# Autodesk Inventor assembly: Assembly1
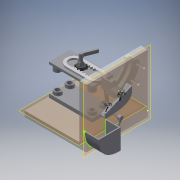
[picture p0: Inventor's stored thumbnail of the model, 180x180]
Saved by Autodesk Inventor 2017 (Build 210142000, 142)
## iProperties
Created: 2017-04
Part Number: Assembly1
Document SubType Name: Assembly
Designer: 1460374
Author: 1460374
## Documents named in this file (18)
- R:\STEM 1st Pd\JacobPatCandy\Assembly1.iam
- R:\STEM 1st Pd\JacobPatCandy\BasePlate.ipt
- R:\STEM 1st Pd\JacobPatCandy\RampV2.ipt
- R:\STEM 1st Pd\JacobPatCandy\RampPlate.ipt
- R:\STEM 1st Pd\JacobPatCandy\platform.ipt
- R:\STEM 1st Pd\JacobPatCandy\guard.ipt
- R:\STEM 1st Pd\JacobPatCandy\Connector.ipt
- R:\STEM 1st Pd\JacobPatCandy\Gearv2.ipt
- R:\STEM 1st Pd\JacobPatCandy\handle.ipt
- R:\STEM 1st Pd\JacobPatCandy\platform2.ipt
- R:\STEM 1st Pd\JacobPatCandy\platform2_2.ipt
- R:\STEM 1st Pd\JacobPatCandy\push.ipt
- R:\STEM 1st Pd\JacobPatCandy\SwirlPiece.ipt
- R:\STEM 1st Pd\JacobPatCandy\SwirlPath.ipt
- R:\STEM 1st Pd\JacobPatCandy\partial_gear.ipt
- R:\STEM 1st Pd\JacobPatCandy\gear handle.ipt
- R:\STEM 1st Pd\JacobPatCandy\SwirlWall.ipt
- R:\STEM 1st Pd\JacobPatCandy\BowlV2.ipt
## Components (17 placed, 17 different names)
1. BasePlate:1 — Mate:8, Mate:9, Mate:10, Mate:11, Mate:12, Mate:23, Mate:28, Mate:31, Mate:32, Mate:35, Flush:5, Mate:47, Mate:50, Flush:19, Flush:20
2. RampV2:1 — Mate:5, Mate:6, Mate:7, Mate:8, Mate:9, Flush:1, Mate:49
3. RampPlate:1 — Mate:5, Mate:6, Mate:7
4. platform:1 — Mate:47, Mate:48, Flush:17, Mate:49
5. guard:1 — Flush:1, Mate:10, Mate:11, Mate:12
6. Connector:1 — Mate:30, Mate:48, Flush:17
7. Gearv2:1 — Mate:23, Mate:25, Mate:26, Mate:28, Mate:30, Mate:32
8. handle:1 — Mate:25, Mate:26, Mate:31
9. platform2:1
10. platform2_2:1 — Mate:44, Mate:45, Mate:46
11. push:1 — Mate:35, Mate:44
12. SwirlPiece:1 — Flush:5
13. SwirlPath:1 — Mate:50, Flush:18
14. partial_gear:1 — Mate:41, Mate:42, Mate:43, Mate:45, Mate:46
15. gear handle:1 — Mate:41, Mate:42, Mate:43
16. SwirlWall:1 — Flush:18
17. BowlV2:1 — Flush:19, Flush:20
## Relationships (32: Mate 26, Flush 6)
- Mate:5: RampV2:1 ↔ RampPlate:1
- Mate:6: RampV2:1 ↔ RampPlate:1
- Mate:7: RampV2:1 ↔ RampPlate:1
- Mate:8: BasePlate:1 ↔ RampV2:1
- Mate:9: BasePlate:1 ↔ RampV2:1
- Flush:1: RampV2:1 ↔ guard:1
- Mate:10: BasePlate:1 ↔ guard:1
- Mate:11: BasePlate:1 ↔ guard:1
- Mate:12: BasePlate:1 ↔ guard:1
- Mate:23: BasePlate:1 ↔ Gearv2:1
- Mate:25: Gearv2:1 ↔ handle:1
- Mate:26: Gearv2:1 ↔ handle:1
- Mate:28: BasePlate:1 ↔ Gearv2:1
- Mate:30: Connector:1 ↔ Gearv2:1
- Mate:31: BasePlate:1 ↔ handle:1
- Mate:32: BasePlate:1 ↔ Gearv2:1
- Mate:35: BasePlate:1 ↔ push:1
- Flush:5: BasePlate:1 ↔ SwirlPiece:1
- Mate:41: partial_gear:1 ↔ gear handle:1
- Mate:42: partial_gear:1 ↔ gear handle:1
- Mate:43: partial_gear:1 ↔ gear handle:1
- Mate:44: platform2_2:1 ↔ push:1
- Mate:45: platform2_2:1 ↔ partial_gear:1
- Mate:46: platform2_2:1 ↔ partial_gear:1
- Mate:47: BasePlate:1 ↔ platform:1
- Mate:48: platform:1 ↔ Connector:1
- Flush:17: platform:1 ↔ Connector:1
- Mate:49: RampV2:1 ↔ platform:1
- Mate:50: BasePlate:1 ↔ SwirlPath:1
- Flush:18: SwirlPath:1 ↔ SwirlWall:1
- Flush:19: BasePlate:1 ↔ BowlV2:1
- Flush:20: BasePlate:1 ↔ BowlV2:1
